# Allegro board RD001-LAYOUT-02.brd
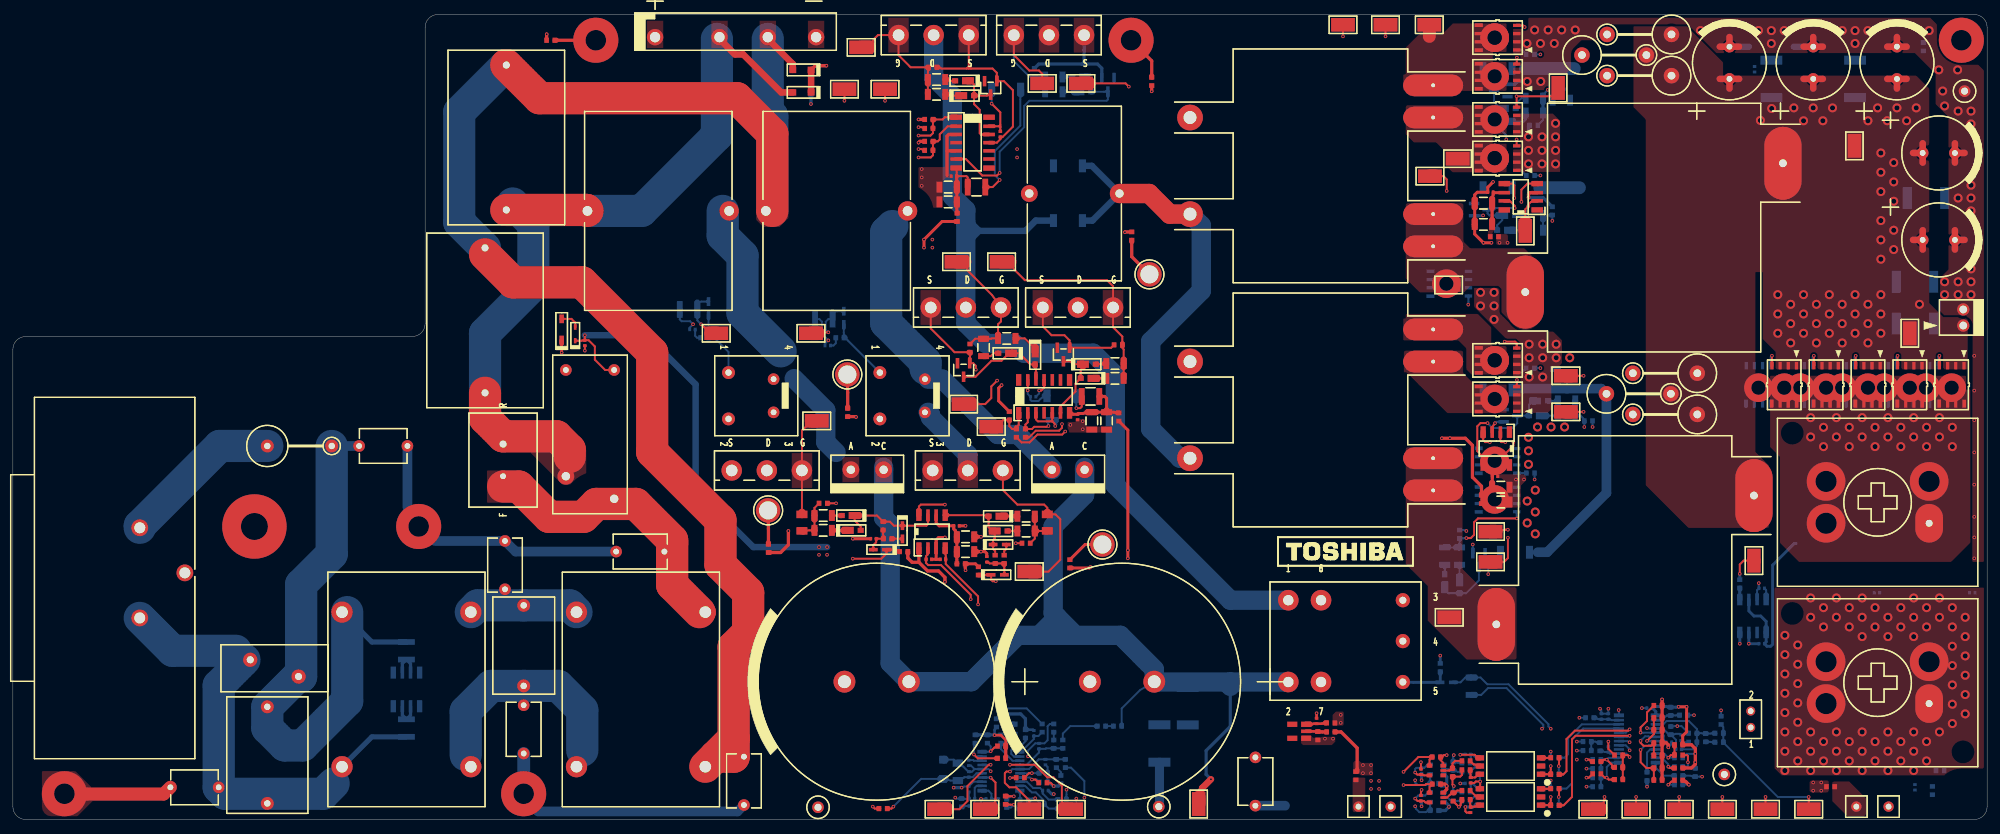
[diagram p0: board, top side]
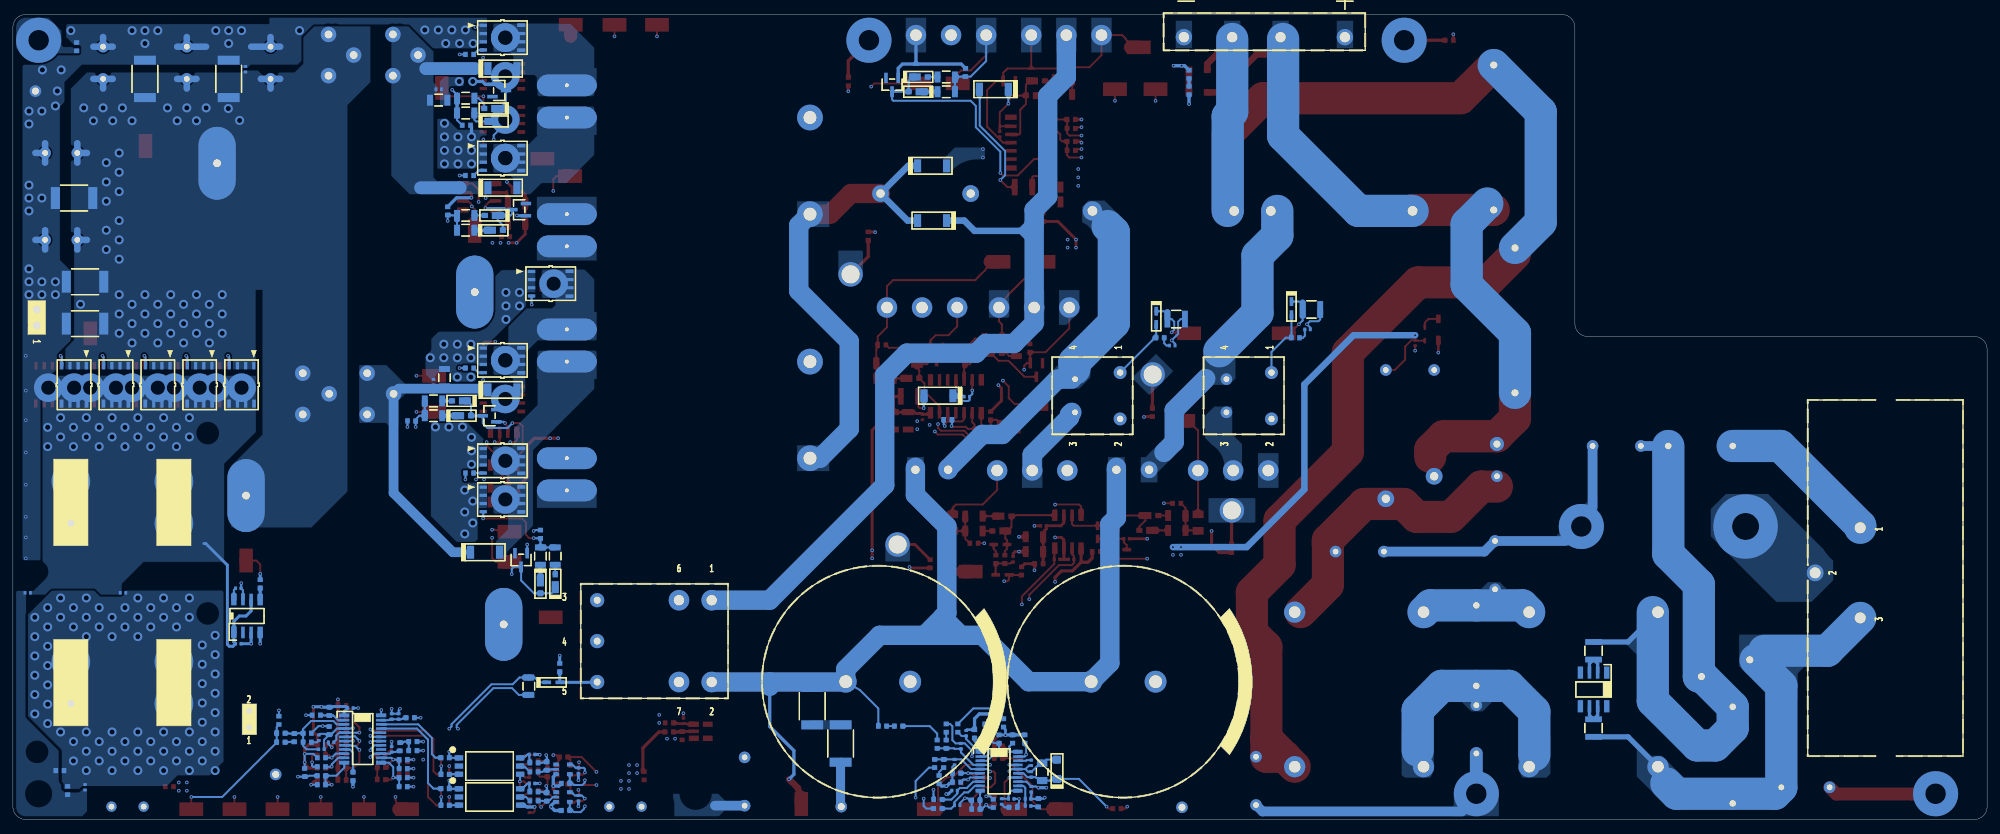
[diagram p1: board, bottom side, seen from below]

Outline 306.5 x 125 mm; copper layers: TOP, CONDUCTIVE2, CONDUCTIVE3, CONDUCTIVE4, CONDUCTIVE5, BOTTOM. Coordinates in mm from the lower left corner of the outline.
Outline path: 0,73 0.03,73.35 0.12,73.68 0.27,74 0.47,74.29 0.71,74.53 1,74.73 1.32,74.88 1.65,74.97 2,75 62,75 62.35,75.03 62.68,75.12 63,75.27 63.29,75.47 63.53,75.71 63.73,76 63.88,76.32 63.97,76.65 64,77 64,123 64.03,123.35 64.12,123.68 64.27,124 64.47,124.29 64.71,124.53 65,124.73 65.32,124.88 65.65,124.97 66,125 304.5,125 304.85,124.97 305.18,124.88 305.5,124.73 305.79,124.53 306.03,124.29 306.23,124 306.38,123.68 306.47,123.35 306.5,123 306.5,2 306.47,1.65 306.38,1.32 306.23,1 306.03,0.71 305.79,0.47 305.5,0.27 305.18,0.12 304.85,0.03 304.5,0 2,0 1.65,0.03 1.32,0.12 1,0.27 0.71,0.47 0.47,0.71 0.27,1 0.12,1.32 0.03,1.65 0,2 0,73

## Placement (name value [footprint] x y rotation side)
C1  -  [FTP_11]  172.2 21.4 0 top
C2  -  [FTP_13]  279.5 120 270 top
C3  -  [FTP_13]  292.5 120 270 top
C4  -  [FTP_13]  301.5 103.5 180 top
C5  -  [FTP_13]  301.5 90 180 top
C6  -  [FTP_13]  266.5 120 270 top
C7  -  [FTP_11]  134.1 21.4 0 top
C18  -  [FTP_65]  153.3 106.4 90 top
C19  -  [FTP_65#2]  158.4 65.65 0 bottom
C20  -  [FTP_67#2]  262.8 12.7 90 bottom
C21  -  [FTP_65#2]  259 12.7 270 bottom
C22  -  [FTP_65#2]  258.6 10.9 0 bottom
C23  -  [FTP_65#2]  246.6 16 90 bottom
C24  -  [FTP_65#2]  247.7 16 90 bottom
C25  -  [FTP_65#2]  257.1 12 0 bottom
C26  -  [FTP_65#2]  247.7 10.9 90 bottom
C27  -  [FTP_65#2]  240.4 113.4 180 bottom
C30  -  [FTP_77]  39.5 10 90 top
C31  -  [FTP_35]  79.3 14 90 top
C32  -  [FTP_35]  76.4 39.5 270 top
C33  -  [FTP_75]  76.6 105.9 270 top
C34  -  [FTP_65#2]  126.5 73.6 180 bottom
C35  -  [FTP_65]  151.2 40.4 270 top
C36  -  [FTP_65#2]  105.5 76.1 180 bottom
C37  -  [FTP_65]  133.6 43.6 0 top
C38  -  [FTP_65#2]  160.3 8.91 270 bottom
C39  -  [FTP_65#2]  159.3 11.4 90 bottom
C40  -  [FTP_67#2]  153.4 12.5 90 bottom
C41  -  [FTP_23]  155.3 14 90 bottom
C42  -  [FTP_65#2]  148.4 4.7 270 bottom
C43  -  [FTP_65#2]  148.9 3.2 180 bottom
C44  -  [FTP_65#2]  148.9 2.1 180 bottom
C45  -  [FTP_65#2]  151.5 3.2 180 bottom
C46  -  [FTP_65#2]  153 2.8 270 bottom
C47  -  [FTP_65#2]  148.4 7 90 bottom
C48  -  [FTP_24]  146.7 7.4 90 bottom
C49  -  [FTP_65#2]  148.4 8.8 270 bottom
C50  -  [FTP_65#2]  158.5 13.4 90 bottom
C51  -  [FTP_65#2]  241.2 67.9 90 bottom
C52  -  [FTP_73]  79.3 27 90 top
C53  -  [FTP_67]  142.2 105.3 0 top
C54  -  [FTP_67]  142.2 108.7 0 top
C55  -  [FTP_65]  146.1 99.9 0 top
C56  -  [FTP_67#2]  161.35 62.1 0 bottom
C57  -  [FTP_67]  154.7 62.7 270 top
C58  -  [FTP_65]  165.3 62.5 90 top
C59  -  [FTP_65#2]  271.5 35.9 0 bottom
C60  -  [FTP_65]  230.1 53.3 180 top
C61  -  [FTP_65]  229.4 97.4 0 top
C62  -  [FTP_65]  146.5 45.6 180 top
C63  -  [FTP_35]  113.5 6 90 top
C64  -  [FTP_35]  97.4 41.6 0 top
C65  -  [FTP_75]  73.3 77.5 270 top
C66  -  [FTP_67]  202.6 13 90 top
C67  -  [FTP_65]  202.4 15.3 270 top
C70  -  [FTP_65]  88.8 74 90 top
C71  -  [FTP_65#2]  225.9 10.1 180 bottom
C72  -  [FTP_65#2]  225.9 5.6 180 bottom
C73  -  [FTP_65]  226.3 6.1 90 top
C74  -  [FTP_65]  226.3 1.5 90 top
C75  -  [FTP_65#2]  160.3 4.5 0 bottom
C76  -  [FTP_65#2]  159.9 2.2 180 bottom
C77  -  [FTP_67#2]  157 3 0 bottom
C78  -  [FTP_33]  57.5 58 180 top
C79  -  [FTP_33]  28.2 5 0 top
C80  -  [FTP_65]  144.4 40.4 0 top
C81  -  [FTP_65]  142.2 40.4 180 top
C82  -  [FTP_15]  147.9 43.9 180 top
C83  -  [FTP_15]  147.9 41.6 180 top
C84  -  [FTP_15]  167.5 61.9 90 top
C85  -  [FTP_15]  169.8 61.9 90 top
C86  -  [FTP_15]  145.2 95.9 0 top
C87  -  [FTP_15]  145.2 98.2 0 top
C88  -  [FTP_15]  228.3 95.7 0 top
C89  -  [FTP_15]  228.3 92.4 0 top
C90  -  [FTP_15]  231 49.3 180 top
C91  -  [FTP_15]  231 51.6 180 top
C92  -  [FTP_65#2]  289.4 35.2 180 bottom
C93  -  [FTP_65#2]  304.2 35.2 0 bottom
C94  -  [FTP_65#2]  295.3 5 90 bottom
C95  -  [FTP_65#2]  218.7 7.6 270 bottom
C96  -  [FTP_65#2]  218.7 3.3 270 bottom
C97  -  [FTP_65]  218.6 7.4 270 top
C98  -  [FTP_65]  218.6 3.3 270 top
C99  -  [FTP_65#2]  254.1 17.3 180 bottom
C100  -  [FTP_65#2]  271.5 27.3 180 bottom
C101  -  [FTP_33]  192.9 5.9 270 top
C102  -  [FTP_65#2]  270.4 116.5 90 bottom
CN1  -  [FTP_9]  3.9 37.5 270 top
CN2  -  [FTP_5]  208.9 2 0 top
CN3  -  [FTP_5]  213.9 2 0 top
CN4  -  [FTP_5]  286.2 2 0 top
CN5  -  [FTP_5]  291.2 2 0 top
CN6  -  [FTP_92]  289.5 49.25 90 top
CN7  -  [FTP_92]  289.5 21.25 90 top
CN8  -  [FTP_3]  302.8 76.7 90 top
CN10  -  [FTP_7]  269.8 14.3 0 top
D1  -  [FTP_53]  130.1 54.31 0 top
D2  -  [FTP_53]  161.3 54.31 0 top
D3  -  [FTP_17]  99.7 121.48 0 top
D8  -  [FTP_29]  122.5 112.9 0 top
D9  -  [FTP_29]  122.5 116.4 0 top
D12  -  [FTP_20]  129 77.9 90 bottom
D13  -  [FTP_20]  108 79.4 90 bottom
D14  -  [FTP_20]  222.6 21.3 0 bottom
D16  -  [FTP_81]  154.2 113.4 180 bottom
D17  -  [FTP_81]  162.8 65.8 180 bottom
D18  -  [FTP_81]  163.8 101.5 0 bottom
D19  -  [FTP_81]  163.8 93 180 bottom
D20  -  [FTP_81]  230.5 98.1 0 bottom
D21  -  [FTP_81]  230.5 116.6 0 bottom
D22  -  [FTP_27]  170 114.1 0 bottom
D23  -  [FTP_27]  151.8 113.6 180 top
D24  -  [FTP_27]  147.6 69.8 180 top
D25  -  [FTP_27]  163.1 72.2 180 top
D26  -  [FTP_27]  227.9 94.7 90 bottom
D27  -  [FTP_27]  231 113.2 270 bottom
D28  -  [FTP_27]  232.5 62.7 90 bottom
D29  -  [FTP_27]  227.6 40.3 0 bottom
D30  -  [FTP_20]  153.2 42.7 180 top
D31  -  [FTP_20]  152.9 38 180 top
D32  -  [FTP_20]  138.1 44.6 90 top
D33  -  [FTP_20]  134.6 41.9 0 top
D34  -  [FTP_81]  233.2 41.5 0 bottom
D35  -  [FTP_81]  230.5 66.7 0 bottom
D36  -  [FTP_83]  152.7 47.1 0 top
D37  -  [FTP_83]  153.2 44.8 180 top
D38  -  [FTP_83]  130.4 44.9 180 top
D39  -  [FTP_83]  129.9 47.2 0 top
D40  -  [FTP_83]  158.7 71.9 90 top
D41  -  [FTP_83]  154.2 72.4 0 top
D42  -  [FTP_83]  148 112.4 180 top
D43  -  [FTP_83]  147.5 114.7 0 top
D44  -  [FTP_83]  167 68.5 0 top
D45  -  [FTP_83]  166.9 70.7 180 top
D46  -  [FTP_83]  166.2 113 180 bottom
D47  -  [FTP_83]  165.7 115.3 0 bottom
D48  -  [FTP_28]  87.3 75.4 270 top
D49  -  [FTP_85]  144.4 7.8 270 bottom
D50  -  [FTP_19]  85.2 76.1 270 top
D51  -  [FTP_83]  231.6 108.4 0 bottom
D52  -  [FTP_83]  232.1 110.4 180 bottom
D53  -  [FTP_83]  231.65 91.5 0 bottom
D54  -  [FTP_83]  232 93.8 180 bottom
D55  -  [FTP_83]  236.6 62.7 0 bottom
D56  -  [FTP_83]  237.1 65 180 bottom
D57  -  [FTP_83]  224.6 36.35 90 bottom
D58  -  [FTP_83]  222.3 36.85 270 bottom
F1  -  [FTP_79]  39.5 58 0 top
FB1  -  [FTP_55]  160.6 46.1 90 top
FB2  -  [FTP_55]  122.5 46.1 90 top
HS1  -  [FTP_116]  129.55 69.1 0 top
HS2  -  [FTP_116]  169.15 42.7 0 top
HS3  -  [FTP_116]  117.25 48 0 top
HS4  -  [FTP_116]  176.45 84.65 0 top
IC1  -  [FTP_60]  61.1 20.2 180 bottom
IC2  -  [FTP_112]  142.7 44.7 0 top
IC3  -  [FTP_128]  153.4 7.5 270 bottom
IC4  -  [FTP_59]  160.1 65.7 0 top
IC5  -  [FTP_59]  149 105.1 270 top
IC6  -  [FTP_112]  234.1 96.7 90 top
IC7  -  [FTP_112]  230.3 57.6 180 top
IC8  -  [FTP_112]  270.15 31.6 180 bottom
IC10  -  [FTP_61]  252.2 12.5 90 bottom
IC11  -  [FTP_38]  199.7 13.7 90 top
IC13  -  [FTP_122]  232.5 8.3 270 bottom
IC14  -  [FTP_122]  232.5 3.5 270 bottom
IC15  -  [FTP_122]  232.5 8.3 90 top
IC16  -  [FTP_122]  232.5 3.5 90 top
IC20  -  [FTP_100]  89.6 59.8 270 top
IC21  -  [FTP_37#2]  221.1 7.8 90 bottom
IC22  -  [FTP_37#2]  221.1 3.5 90 bottom
IC23  -  [FTP_37]  221 7.6 90 top
IC24  -  [FTP_37]  221 3.4 90 top
L1  -  [FTP_118]  100.2 94.5 270 top
L2  -  [FTP_118]  127.9 94.5 270 top
L3  -  [FTP_69]  164.8 97.2 270 top
L5  -  [FTP_124]  250.3 40.3 270 top
L6  -  [FTP_124]  254.8 91.9 270 top
L11  -  [FTP_110]  61.1 20.2 270 top
L12  -  [FTP_110]  97.5 20.2 270 top
NOREF  -  []  302.5 121 0 top
NOREF#2  -  []  173.6 121 0 top
NOREF#3  -  []  196.4 39.4 0 top
NOREF#4  -  []  90.5 121 0 top
NOREF#5  -  []  200.5 4 0 top
NOREF#6  -  []  302.5 4 0 top
NOREF#7  -  []  63 45.5 0 top
NOREF#8  -  []  37.5 45.5 0 top
NOREF#9  -  []  8 4 0 top
NOREF#10  -  []  8 71 0 top
NOREF#11  -  []  79.3 4 0 top
Q1  -  [FTP_102]  111.6 54.2 0 top
Q2  -  [FTP_102]  142.8 54.2 0 top
Q3  -  [FTP_102]  142.5 79.5 0 top
Q4  -  [FTP_102]  159.9 79.5 0 top
Q5  -  [FTP_102]  148.4 121.8 180 top
Q6  -  [FTP_102]  166.3 121.8 180 top
Q7  -  [FTP_1]  230.5 71.3 90 top
Q8  -  [FTP_1]  223 83.2 270 bottom
Q9  -  [FTP_1]  230.5 49.7 270 bottom
Q10  -  [FTP_1]  230.5 55.7 270 bottom
Q11  -  [FTP_1]  230.5 121.4 90 top
Q12  -  [FTP_1]  230.5 115.4 90 top
Q13  -  [FTP_1]  230.5 108.7 90 top
Q14  -  [FTP_1]  230.5 102.7 270 bottom
Q15  -  [FTP_1]  301 67.5 180 top
Q16  -  [FTP_1]  294.5 67.5 180 top
Q17  -  [FTP_1]  288 67.5 180 top
Q18  -  [FTP_1]  281.5 67.5 180 top
Q19  -  [FTP_1]  275 67.5 180 top
Q20  -  [FTP_1]  297 67.5 0 bottom
Q21  -  [FTP_1]  290.5 67.5 0 bottom
Q22  -  [FTP_1]  284 67.5 0 bottom
Q23  -  [FTP_1]  277.5 67.5 0 bottom
Q24  -  [FTP_1]  271 67.5 0 bottom
Q25  -  [FTP_1]  230.5 121.4 270 bottom
Q26  -  [FTP_1]  230.5 102.7 90 top
Q27  -  [FTP_1]  230.5 65.3 90 top
Q28  -  [FTP_1]  230.5 71.3 270 bottom
R1  -  [FTP_67#2]  163.4 8.7 90 bottom
R2  -  [FTP_67#2]  162.7 6.2 270 bottom
R6  -  [FTP_67#2]  268.1 36.6 270 bottom
R7  -  [FTP_49#2]  104.9 79.2 180 bottom
R8  -  [FTP_49#2]  125.9 77.7 180 bottom
R9  -  [FTP_67#2]  221.6 23.6 90 bottom
R18  -  [FTP_50#2]  236.2 109.7 180 bottom
R19  -  [FTP_67#2]  236.1 107.8 180 bottom
R20  -  [FTP_50#2]  236.2 91.5 180 bottom
R21  -  [FTP_67#2]  239 94.5 90 bottom
R22  -  [FTP_67#2]  244.6 61.9 0 bottom
R23  -  [FTP_50#2]  241.2 62.7 180 bottom
R24  -  [FTP_50#2]  224.6 40.9 270 bottom
R25  -  [FTP_67#2]  224.6 44.3 90 bottom
R28  -  [FTP_67]  142.8 116.8 180 top
R29  -  [FTP_67#2]  158.6 116 90 bottom
R31  -  [FTP_67]  148.6 73.2 90 top
R33  -  [FTP_67]  171.6 73.7 0 top
R42  -  [FTP_67#2]  264.9 13.4 180 bottom
R43  -  [FTP_67#2]  260.8 13.4 180 bottom
R44  -  [FTP_67#2]  257.4 16.8 270 bottom
R45  -  [FTP_67#2]  259.4 16.2 0 bottom
R46  -  [FTP_67#2]  264.9 12 180 bottom
R47  -  [FTP_67#2]  260.8 12 180 bottom
R48  -  [FTP_67#2]  257.4 13.8 90 bottom
R49  -  [FTP_67#2]  244.8 15.8 180 bottom
R50  -  [FTP_67]  255.4 17.7 180 top
R51  -  [FTP_67]  255.4 9.9 180 top
R52  -  [FTP_67]  255.4 13.9 180 top
R53  -  [FTP_67]  255.4 8 180 top
R54  -  [FTP_67#2]  253.7 6.7 270 bottom
R55  -  [FTP_67]  258.6 10 180 top
R56  -  [FTP_67#2]  258.6 8.2 0 bottom
R57  -  [FTP_67#2]  258.6 9.6 180 bottom
R58  -  [FTP_67]  258.6 8 0 top
R59  -  [FTP_67#2]  244.4 12.1 180 bottom
R60  -  [FTP_67#2]  258.6 6.8 180 bottom
R61  -  [FTP_67#2]  258.6 5.4 0 bottom
R62  -  [FTP_67#2]  261.2 7.3 270 bottom
R63  -  [FTP_67]  249.3 6.2 0 top
R64  -  [FTP_67#2]  245.9 6.5 180 bottom
R65  -  [FTP_67]  249.3 8.1 0 top
R66  -  [FTP_67#2]  245.9 9.3 180 bottom
R67  -  [FTP_67#2]  244.4 10.7 0 bottom
R69  -  [FTP_67#2]  246.4 11.3 270 bottom
R70  -  [FTP_67]  249.3 10 0 top
R71  -  [FTP_67]  157.3 42.9 0 top
R72  -  [FTP_50]  157.3 47.1 0 top
R73  -  [FTP_67]  125.8 49.1 180 top
R74  -  [FTP_50]  125.8 44.9 180 top
R75  -  [FTP_67#2]  265.2 15.4 270 bottom
R76  -  [FTP_50#2]  240.4 111.7 180 bottom
R77  -  [FTP_98]  257.5 121.9 180 top
R78  -  [FTP_98]  257.5 115.5 180 top
R79  -  [FTP_49#2]  61.1 26.2 270 bottom
R80  -  [FTP_49#2]  61.1 14.2 270 bottom
R81  -  [FTP_67#2]  128.4 74.8 180 bottom
R82  -  [FTP_67]  152.5 40.4 270 top
R83  -  [FTP_67]  149.9 38.6 90 top
R85  -  [FTP_67#2]  107.4 74.8 180 bottom
R86  -  [FTP_67]  135.1 45.6 270 top
R87  -  [FTP_67]  138.3 41.6 0 top
R89  -  [FTP_67#2]  163 11.7 270 bottom
R90  -  [FTP_67#2]  161.6 14.2 90 bottom
R91  -  [FTP_67#2]  169 14.5 180 bottom
R92  -  [FTP_67#2]  171.5 14.5 180 bottom
R93  -  [FTP_67#2]  152.7 15 270 bottom
R94  -  [FTP_67#2]  123.9 113.2 270 bottom
R95  -  [FTP_67#2]  123.9 115.7 270 bottom
R96  -  [FTP_67#2]  157 1.6 0 bottom
R97  -  [FTP_67#2]  154.3 2.5 270 bottom
R98  -  [FTP_67#2]  147.3 2.6 90 bottom
R99  -  [FTP_67#2]  151.2 1.9 180 bottom
R100  -  [FTP_67#2]  149.4 12.5 90 bottom
R101  -  [FTP_67#2]  160 5.8 0 bottom
R102  -  [FTP_67#2]  160 7.2 0 bottom
R103  -  [FTP_67#2]  151.3 12.5 90 bottom
R104  -  [FTP_67#2]  157.2 13.3 90 bottom
R105  -  [FTP_50#2]  239.5 68.6 90 bottom
R106  -  [FTP_98]  261.5 69.3 180 top
R107  -  [FTP_98]  247.4 66.1 0 top
R108  -  [FTP_50]  157.3 44.8 0 top
R109  -  [FTP_50]  125.8 47.2 180 top
R110  -  [FTP_67]  142.2 103.9 0 top
R111  -  [FTP_67]  142.2 107.3 0 top
R112  -  [FTP_67]  157.2 60 90 top
R113  -  [FTP_67]  155.8 60 90 top
R114  -  [FTP_49]  149.6 98.2 0 top
R115  -  [FTP_49]  167.3 65.7 180 top
R116  -  [FTP_67]  208.5 6.8 90 top
R117  -  [FTP_67]  204.6 15 0 top
R118  -  [FTP_67]  282.2 5.1 180 top
R120  -  [FTP_67]  135.1 1.7 0 top
R121  -  [FTP_67]  147.2 39.7 180 top
R122  -  [FTP_67]  171.7 62.5 90 top
R123  -  [FTP_67]  146.6 93.5 90 top
R124  -  [FTP_67]  228 49.7 270 top
R125  -  [FTP_67]  230 90.5 180 top
R126  -  [FTP_50]  154.3 74.7 180 top
R127  -  [FTP_50]  150.7 73.3 90 top
R128  -  [FTP_98]  243.6 118.7 0 top
R129  -  [FTP_98]  261.5 62.9 180 top
R130  -  [FTP_67]  204.6 13.6 180 top
R132  -  [FTP_50]  143.4 112.6 180 top
R133  -  [FTP_50]  143.4 114.9 180 top
R134  -  [FTP_50]  171.1 68.5 0 top
R135  -  [FTP_50]  171.1 70.8 0 top
R136  -  [FTP_50#2]  161.6 113 0 bottom
R137  -  [FTP_50#2]  161.6 115.3 0 bottom
R138  -  [FTP_108]  76.1 55.8 90 top
R149  -  [FTP_67#2]  239.4 9.6 180 bottom
R150  -  [FTP_67#2]  239.4 4.8 180 bottom
R151  -  [FTP_67]  239.4 7 0 top
R152  -  [FTP_67]  239.4 2.2 0 top
R153  -  [FTP_67#2]  225.6 7.4 180 bottom
R154  -  [FTP_67#2]  225.6 2.9 180 bottom
R155  -  [FTP_67]  225.6 9.1 0 top
R156  -  [FTP_67]  225.6 4.5 0 top
R157  -  [FTP_67#2]  225.6 8.8 180 bottom
R160  -  [FTP_67#2]  225.6 4.3 180 bottom
R163  -  [FTP_67]  225.6 7.7 0 top
R166  -  [FTP_67]  225.6 3.1 0 top
R169  -  [FTP_67#2]  162.9 3.1 0 bottom
R170  -  [FTP_67#2]  162.9 1.7 0 bottom
R171  -  [FTP_67#2]  159.8 14.2 270 bottom
R172  -  [FTP_67]  153.9 40.4 270 top
R173  -  [FTP_67]  135.8 43.6 180 top
R174  -  [FTP_67]  153.5 11.4 180 top
R175  -  [FTP_67]  156.4 6.5 0 top
R176  -  [FTP_67]  159.9 5.7 180 top
R177  -  [FTP_67]  154.1 3 90 top
R178  -  [FTP_106]  182.4 17.6 270 bottom
R179  -  [FTP_106]  178 11.8 270 bottom
R180  -  [FTP_67]  255.4 11.9 180 top
R181  -  [FTP_67]  255.4 15.8 180 top
R182  -  [FTP_67]  255.4 6.1 180 top
R184  -  [FTP_67]  258.6 6.1 180 top
R185  -  [FTP_50#2]  226.4 20.7 270 bottom
R186  -  [FTP_67#2]  223.6 8.3 270 bottom
R187  -  [FTP_67#2]  220.7 5.6 0 bottom
R188  -  [FTP_67#2]  223.6 3.5 270 bottom
R189  -  [FTP_67#2]  220.7 1.4 0 bottom
R190  -  [FTP_67]  223.5 7.3 270 top
R191  -  [FTP_67]  221 9.7 180 top
R192  -  [FTP_67]  223.6 3.5 270 top
R193  -  [FTP_67]  221 5.5 180 top
R194  -  [FTP_67#2]  239.4 7 180 bottom
R195  -  [FTP_67#2]  239.4 2.2 180 bottom
R196  -  [FTP_67]  239.4 9.6 0 top
R197  -  [FTP_67]  239.4 4.8 0 top
R198  -  [FTP_67]  153.5 9.5 180 top
R199  -  [FTP_106]  295.3 77 0 bottom
R200  -  [FTP_106]  273 115 90 bottom
R201  -  [FTP_106]  286 115 90 bottom
R202  -  [FTP_106]  295.3 83.5 0 bottom
R203  -  [FTP_106]  297 96.5 0 bottom
R204  -  [FTP_67#2]  296.6 120 270 bottom
R205  -  [FTP_67#2]  299.2 7.6 0 bottom
R206  -  [FTP_67#2]  298 4.5 270 bottom
R207  -  [FTP_67]  258.6 11.6 0 top
R208  -  [FTP_67]  245.9 7.1 0 top
R209  -  [FTP_67]  245.9 9 0 top
R210  -  [FTP_67#2]  245.9 5.1 0 bottom
R211  -  [FTP_67#2]  245.9 7.9 0 bottom
R212  -  [FTP_50#2]  236.2 112 180 bottom
R213  -  [FTP_50#2]  236.2 93.8 180 bottom
R214  -  [FTP_50#2]  241.2 65 180 bottom
R215  -  [FTP_50#2]  222.3 40.9 270 bottom
R216  -  [FTP_67#2]  235.6 118.8 0 bottom
R217  -  [FTP_67#2]  235.6 100 0 bottom
R218  -  [FTP_67#2]  235.6 70.1 0 bottom
R219  -  [FTP_67#2]  235.6 53.8 0 bottom
R220  -  [FTP_67]  129.6 63.2 90 top
R221  -  [FTP_67]  164.1 39.7 90 top
R222  -  [FTP_67]  117.3 42.1 90 top
R223  -  [FTP_67]  173.7 90.6 270 top
R224  -  [FTP_67]  176.8 114.6 90 top
R225  -  [FTP_67]  83.5 121 0 top
R227  -  [FTP_67#2]  161.6 11.7 90 bottom
R228  -  [FTP_67#2]  162 8.7 270 bottom
RV1  -  [FTP_120]  40.6 23.5 180 top
T2  -  [FTP_94]  138.9 65.8 270 top
T3  -  [FTP_94]  115.4 65.8 270 top
T4  -  [FTP_96]  206.9 27.7 0 top
T5  -  [FTP_126]  203 63.6 0 top
T6  -  [FTP_126]  203 101.5 0 top
TP1  -  [FTP_57]  123.9 75.5 0 top
TP2  -  [FTP_57]  109.2 75.5 0 top
TP3  -  [FTP_57]  157.8 38.5 0 top
TP4  -  [FTP_57]  124.8 61.9 0 top
TP5  -  [FTP_57]  150.9 1.6 0 top
TP6  -  [FTP_57]  143.8 1.6 0 top
TP7  -  [FTP_57]  157.8 1.6 0 top
TP8  -  [FTP_57]  164.3 1.6 0 top
TP9  -  [FTP_57]  151.9 61 0 top
TP10  -  [FTP_57]  147.6 64.5 0 top
TP11  -  [FTP_57]  146.5 86.6 0 top
TP12  -  [FTP_57]  153.5 86.6 0 top
TP13  -  [FTP_57]  131.7 119.9 0 top
TP14  -  [FTP_57]  159.8 114.3 180 top
TP15  -  [FTP_57]  165.8 114.3 0 top
TP17  -  [FTP_57]  222.9 83 0 top
TP18  -  [FTP_57]  223 31.4 180 top
TP19  -  [FTP_57]  239.9 113.6 90 top
TP20  -  [FTP_57]  241.1 63.3 0 top
TP21  -  [FTP_57]  213.1 123.4 0 top
TP22  -  [FTP_57]  241.1 68.9 0 top
TP23  -  [FTP_57]  234.8 91.4 270 top
TP24  -  [FTP_57]  220 99.9 0 top
TP25  -  [FTP_57]  229.4 40 0 top
TP26  -  [FTP_57]  229.4 44.7 0 top
TP27  -  [FTP_57]  206.5 123.4 0 top
TP28  -  [FTP_57]  270.3 40.2 90 top
TP29  -  [FTP_57]  224.3 102.6 0 top
TP30  -  [FTP_57]  219.9 123.4 0 top
TP31  -  [FTP_57]  294.5 75.5 90 top
TP32  -  [FTP_57]  272.1 1.6 0 top
TP33  -  [FTP_57]  278.8 1.6 0 top
TP34  -  [FTP_57]  265.4 1.6 0 top
TP35  -  [FTP_57]  252 1.6 0 top
TP36  -  [FTP_57]  258.7 1.6 0 top
TP37  -  [FTP_57]  245.3 1.6 0 top
TP38  -  [FTP_57]  135.4 113.4 0 top
TP39  -  [FTP_57]  129.1 113.4 0 top
TP40  -  [FTP_57]  285.9 104.6 90 top
TP41  -  [FTP_71]  303 113.1 0 top
TP42  -  [FTP_71]  265.7 7 0 top
TP43  -  [FTP_71]  125 1.9 0 top
TP44  -  [FTP_57]  184.1 2.4 90 top
TP45  -  [FTP_71]  177.9 2 0 top

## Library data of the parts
C1 C7 = PRT_4: alternate symbols: (T:FTP_11;B:FTP_12)
C2-C6 = PRT_3: alternate symbols: (T:FTP_13;B:FTP_14)
C18 C19 C21-C27 C34-C39 C42-C47 C49-C51 C55 C58-C62 C67 C70-C76 C80 C81 C92-C100 C102 = PRT_52: alternate symbols: (T:FTP_65;B:FTP_66)
C20 C40 C53 C54 C56 C57 C66 C77 = PRT_48: alternate symbols: (T:FTP_67;B:FTP_68)
C30 = PRT_19: alternate symbols: (T:FTP_77;B:FTP_78)
C31 C32 C63 C64 = PRT_13: alternate symbols: (T:FTP_35;B:FTP_36)
C33 C65 = PRT_18: alternate symbols: (T:FTP_75;B:FTP_76)
C41 = PRT_32: alternate symbols: (T:FTP_23,FTP_44;B:FTP_26,FTP_48)
C48 = PRT_51: alternate symbols: (T:FTP_24;B:FTP_25)
C52 = PRT_17: alternate symbols: (T:FTP_73;B:FTP_74)
C78 C79 = PRT_29: alternate symbols: (T:FTP_33;B:FTP_34)
C82-C91 = PRT_46: alternate symbols: (T:FTP_15;B:FTP_16)
C101 = PRT_50: alternate symbols: (T:FTP_33;B:FTP_34)
CN1 = PRT_61: alternate symbols: (T:FTP_9;B:FTP_10)
CN2-CN5 = PRT_57: alternate symbols: (T:FTP_5;B:FTP_6)
CN6 CN7 = PRT_38: alternate symbols: (T:FTP_92;B:FTP_93)
CN8 = PRT_42: alternate symbols: (T:FTP_3;B:FTP_4)
CN10 = PRT_56: alternate symbols: (T:FTP_7;B:FTP_8)
D1 D2 = PRT_12: alternate symbols: (T:FTP_53;B:FTP_54)
D3 = PRT_53: alternate symbols: (T:FTP_17,FTP_18;B:FTP_87,FTP_88)
D8 D9 = PRT_24: alternate symbols: (T:FTP_29;B:FTP_30)
D12-D14 D30-D33 = PRT_27: alternate symbols: (T:FTP_20;B:FTP_22)
D16-D21 D34 D35 = PRT_14: alternate symbols: (T:FTP_81;B:FTP_82)
D22-D29 = PRT_25: alternate symbols: (T:FTP_27,FTP_41;B:FTP_31,FTP_45)
D36-D47 D51-D58 = PRT_11: alternate symbols: (T:FTP_83;B:FTP_84)
D48 = PRT_26: alternate symbols: (T:FTP_28;B:FTP_32)
D49 = PRT_6: alternate symbols: (T:FTP_85;B:FTP_86)
D50 = PRT_47: alternate symbols: (T:FTP_19;B:FTP_21)
F1 = PRT_21: alternate symbols: (T:FTP_79;B:FTP_80)
FB1 FB2 = PRT_30: alternate symbols: (T:FTP_55;B:FTP_56)
HS1-HS4 = PRT_39: alternate symbols: (T:FTP_116;B:FTP_117)
IC1 = PRT_45: alternate symbols: (T:FTP_60;B:FTP_63)
IC2 IC6 IC7 = PRT_63: alternate symbols: (T:FTP_112;B:FTP_113)
IC3 = PRT_59: alternate symbols: (T:FTP_128;B:FTP_129)
IC4 IC5 = PRT_58: alternate symbols: (T:FTP_59;B:FTP_62)
IC8 = PRT_62: alternate symbols: (T:FTP_112;B:FTP_113)
IC10 = PRT_16: alternate symbols: (T:FTP_61;B:FTP_64)
IC11 = PRT_10: alternate symbols: (T:FTP_38,FTP_42;B:FTP_40,FTP_46)
IC13-IC16 = PRT_15: alternate symbols: (T:FTP_122;B:FTP_123)
IC20 = PRT_1: alternate symbols: (T:FTP_100;B:FTP_101)
IC21-IC24 = PRT_2: alternate symbols: (T:FTP_37,FTP_43;B:FTP_39,FTP_47)
L1 L2 = PRT_41: alternate symbols: (T:FTP_118;B:FTP_119)
L3 = PRT_64: alternate symbols: (T:FTP_69;B:FTP_70)
L5 L6 = PRT_40: alternate symbols: (T:FTP_124;B:FTP_125)
L11 L12 = PRT_22: alternate symbols: (T:FTP_110;B:FTP_111)
Q1 Q2 = PRT_31: alternate symbols: (T:FTP_102,FTP_105,FTP_103;B:FTP_89,FTP_104,FTP_90)
Q3-Q6 = PRT_9: alternate symbols: (T:FTP_102,FTP_105,FTP_103;B:FTP_89,FTP_104,FTP_90)
Q7-Q14 Q25-Q28 = PRT_67: alternate symbols: (T:FTP_1;B:FTP_2)
Q15-Q24 = PRT_60: alternate symbols: (T:FTP_1;B:FTP_2)
R1 R2 R6 R9 R19 R21 R22 R25 R28 R29 R31 R33 R42-R67 R69-R71 R73 R75 R81-R83 R85-R87 R89-R104 R110-R113 R116-R118 R120-R125 R130 R149-R157 R160 R163 R166 R169-R177 R180-R182 R184 R186-R198 R204-R211 R216-R225 R227 R228 = PRT_8: alternate symbols: (T:FTP_67;B:FTP_68)
R7 R8 R79 R80 R114 R115 = PRT_23: alternate symbols: (T:FTP_49;B:FTP_52)
R18 R20 R23 R24 R72 R74 R76 R105 R108 R109 R126 R127 R132-R137 R185 R212-R215 = PRT_5: alternate symbols: (T:FTP_50;B:FTP_51)
R77 R78 R106 R107 R128 R129 = PRT_54: alternate symbols: (T:FTP_98;B:FTP_99)
R138 = PRT_33: alternate symbols: (T:FTP_108;B:FTP_109)
R178 R179 R199-R203 = PRT_43: alternate symbols: (T:FTP_106;B:FTP_107)
RV1 = PRT_37: alternate symbols: (T:FTP_120;B:FTP_121)
T2 T3 = PRT_7: alternate symbols: (T:FTP_94;B:FTP_95)
T4 = PRT_65: alternate symbols: (T:FTP_96;B:FTP_97)
T5 T6 = PRT_55: alternate symbols: (T:FTP_126;B:FTP_127)
TP1-TP15 TP17-TP40 TP44 = PRT_44: alternate symbols: (T:FTP_57;B:FTP_58)
TP41 TP42 = PRT_34: alternate symbols: (T:FTP_71;B:FTP_72)
TP43 TP45 = PRT_49: alternate symbols: (T:FTP_71;B:FTP_72)

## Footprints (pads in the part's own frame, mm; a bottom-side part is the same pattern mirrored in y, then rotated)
FTP_1
  rect 0.5x1.15 smd: 1(-1.905,-2.975) 2(-0.635,-2.975) 3(0.635,-2.975) 4(1.905,-2.975)
  rect 0.57x1.25 smd: 5(1.94,2.925) 8(-1.94,2.925)
  rect 0.5x1.25 smd: 6(0.635,2.925) 7(-0.635,2.925)
FTP_3
  round 1.9 hole 1.2: 1(0,0) 2(2.5,0)
FTP_5
  round 1.6 hole 0.9: 1(0,0)
FTP_7
  round 1.4 hole 0.9: 1(0,0) 2(0,2.54)
FTP_9
  round 2.6 hole 1.7: 1(-7.8,15.8) 2(-0.8,22.8) 3(6.2,15.8)
FTP_11
  round 3.4 hole 2: 1(-5,0) 2(5,0)
FTP_13
  round 1.8 hole 0.9: 1(0,0) 2(5,0)
FTP_15
  rect 0.92x1.7 smd: 1(-1.35,0) 2(1.35,0)
FTP_17
  round 2.54 hole 1.6: 1(0,0) 2(10,0) 3(17.5,0) 4(25,0)
FTP_19
  rect 1.335x0.7 smd: A(-1.637,0) C(1.637,0)
FTP_20
  rect 1.36x0.55 smd: A(-1.025,0) C(1.025,0)
FTP_23
  rect 0.83x1.35 smd: 1(0.8,0) 2(-0.8,0)
FTP_24
  rect 1.1x1.6 smd: 1(1.35,0) 2(-1.35,0)
FTP_27
  rect 0.55x1.61 smd: A(-0.95,-1.05) C(0,1.05) NC(0.95,-1.05)
FTP_28
  rect 0.824x0.4 smd: A(-1.05,0) C(1.05,0)
FTP_29
  rect 1.074x1 smd: A(-1.425,0) C(1.425,0)
FTP_33
  round 1.8 hole 0.9: 1(-3.75,0) 2(3.75,0)
FTP_35
  round 1.8 hole 0.9: 1(-3.75,0) 2(3.75,0)
FTP_37
  rect 0.6x0.88 smd: 1(-0.75,-1.065) 3(0.75,-1.065) 4(0.75,1.065) 5(-0.75,1.065)
  rect 0.4x0.88 smd: 2(0,-1.065)
FTP_37#2
  rect 0.6x0.88 smd: 1(0.75,1.065) 3(-0.75,1.065) 4(-0.75,-1.065) 5(0.75,-1.065)
  rect 0.4x0.88 smd: 2(0,1.065)
FTP_38
  rect 0.825x1.56 smd: 1(-1.087,-1.075) 3(1.087,-1.075) 4(1.087,1.075) 5(-1.087,1.075)
  rect 0.55x1.56 smd: 2(0,-1.075)
FTP_49
  rect 0.895x2.6 smd: 1(-1.363,0) 2(1.363,0)
FTP_49#2
  rect 0.895x2.6 smd: 1(1.363,0) 2(-1.363,0)
FTP_50
  rect 0.92x1.7 smd: 1(-1.35,0) 2(1.35,0)
FTP_50#2
  rect 0.92x1.7 smd: 1(1.35,0) 2(-1.35,0)
FTP_53
  round 2.6 hole 1.3: A(0,0) C(5.08,0)
FTP_55
  rect 1.17x1.7 smd: 1(-1.275,0) 2(1.275,0)
FTP_57
  rect 3.7x2.1 smd: 1(0,0)
FTP_59
  rect 0.825x1.805 smd: 1(-3.947,-2.553) 7(3.947,-2.553) 8(3.947,2.553) 14(-3.947,2.553)
  rect 0.55x1.805 smd: 2(-2.54,-2.553) 3(-1.27,-2.553) 4(0,-2.553) 5(1.27,-2.553) 6(2.54,-2.553) 9(2.54,2.553) 10(1.27,2.553) 11(0,2.553) 12(-1.27,2.553) 13(-2.54,2.553)
FTP_60
  rect 0.825x1.885 smd: 1(2.042,2.612) 4(-2.042,2.612) 5(-2.042,-2.612) 8(2.042,-2.612)
  rect 0.55x1.885 smd: 2(0.635,2.612) 3(-0.635,2.612) 6(-0.635,-2.612) 7(0.635,-2.612)
FTP_61
  rect 0.6x1.585 smd: 1(3.675,2.862) 12(-3.675,2.862) 13(-3.675,-2.862) 24(3.675,-2.862)
  rect 0.4x1.585 smd: 2(2.925,2.862) 3(2.275,2.862) 4(1.625,2.862) 5(0.975,2.862) 6(0.325,2.862) 7(-0.325,2.862) 8(-0.975,2.862) 9(-1.625,2.862) 10(-2.275,2.862) 11(-2.925,2.862) 14(-2.925,-2.862) 15(-2.275,-2.862) 16(-1.625,-2.862) 17(-0.975,-2.862) 18(-0.325,-2.862) 19(0.325,-2.862) 20(0.975,-2.862) 21(1.625,-2.862) 22(2.275,-2.862) 23(2.925,-2.862)
FTP_65
  rect 0.45x0.55 smd: 1(-0.425,0) 2(0.425,0)
FTP_65#2
  rect 0.45x0.55 smd: 1(0.425,0) 2(-0.425,0)
FTP_67
  rect 0.72x0.8 smd: 1(-0.64,0) 2(0.64,0)
FTP_67#2
  rect 0.72x0.8 smd: 1(0.64,0) 2(-0.64,0)
FTP_69
  round 2.6 hole 1.3: 1(0,-7) 2(0,7)
FTP_71
  round 1.8 hole 1.1: 1(0,0)
FTP_73
  round 2 hole 1: 1(-6.25,0) 2(6.25,0)
FTP_75
  round 2.2 hole 1.1: 1(-11.25,0) 2(11.25,0)
FTP_77
  round 2 hole 1: 1(-7.5,0) 2(7.5,0)
FTP_79
  round 2 hole 1: 1(0,0) 2(10,0)
FTP_81
  rect 1.1x2 smd: A(-2.25,0) C(2.25,0)
FTP_83
  rect 0.95x0.8 smd: A(-1.225,0)
  rect 1.85x1.1 smd: C(0.775,0)
FTP_85
  rect 1.212x1.2 smd: A(-1.494,0) C(1.494,0)
FTP_92
  custom 1.075x1.075 hole 5x3.3: 1(-3.25,-8)
FTP_94
  round 2 hole 1: 1(-3.6,-4.3) 2(3.6,-4.3)
  round 1.8 hole 0.9: 3(2.575,2.7) 4(-2.575,2.7)
FTP_96
  round 3.2 hole 1.6: 1(-8.89,6.35) 2(-8.89,-6.35) 6(-3.81,6.35) 7(-3.81,-6.35)
  round 2.2 hole 1.1: 3(8.89,6.35) 4(8.89,0) 5(8.89,-6.35)
FTP_98
  round 2.4 hole 1.2: 1(0,0) 2(10,0)
FTP_100
  round 1.8 hole 0.9: 1(-10,3.75) 2(-10,-3.75)
  round 2.6 hole 1.3: 3(6.5,-3.75) 4(10,3.75)
FTP_102
  round 3.175 hole 1.8: D(5.45,0) G(10.9,0) S(0,0)
FTP_106
  rect 1.405x3.4 smd: 1(2.902,0) 2(-2.902,0)
FTP_108
  round 1.8 hole 0.9: 1(-2.5,0)
  round 2.2 hole 1.1: 2(2.5,0)
FTP_110
  round 3.3 hole 1.8: 1(-12,10) 2(-12,-10) 3(12,-10) 4(12,10)
FTP_112
  rect 0.825x1.795 smd: 1(-2.042,-2.558) 4(2.042,-2.558) 5(2.042,2.558) 8(-2.042,2.558)
  rect 0.55x1.795 smd: 2(-0.635,-2.558) 3(0.635,-2.558) 6(0.635,2.558) 7(-0.635,2.558)
FTP_116
  round 3.8 hole 2.8: 1(0,0)
FTP_118
  round 3 hole 1.5: 1(0,-11) 2(0,11)
FTP_120
  round 2.2 hole 1.1: 1(-3.75,1.3) 2(3.75,-1.3)
FTP_122
  rect 0.8x1.3 smd: 1(-1.27,-4.75) 2(0,-4.75) 3(1.27,-4.75) 4(1.27,4.75) 5(0,4.75) 6(-1.27,4.75)
FTP_124
  custom 1.2x1.2 hole 10.3x3.8: 1(10,-20) 2(-10,20)
FTP_126
  round 4 hole 2: 1(-20.25,7.5) 2(-20.25,-7.5)
  custom 0.6x0.6 hole 8.3x1.4: 3(17.5,-12.5) 4(17.5,-7.5) 5(17.5,7.5) 6(17.5,12.5)
FTP_128
  rect 0.6x1.46 smd: 1(-3.025,-2.925) 10(3.025,-2.925) 11(3.025,2.925) 20(-3.025,2.925)
  rect 0.4x1.46 smd: 2(-2.275,-2.925) 3(-1.625,-2.925) 4(-0.975,-2.925) 5(-0.325,-2.925) 6(0.325,-2.925) 7(0.975,-2.925) 8(1.625,-2.925) 9(2.275,-2.925) 12(2.275,2.925) 13(1.625,2.925) 14(0.975,2.925) 15(0.325,2.925) 16(-0.325,2.925) 17(-0.975,2.925) 18(-1.625,2.925) 19(-2.275,2.925)

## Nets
P12V: C92.2(TP-1) C93.2(TP-1) C100.2(TP-1) CN6.1 IC8.1 IC8.6 Q15.5 Q15.6 Q15.7 Q15.8 Q16.5 Q16.6 Q16.7 Q16.8 Q17.5 Q17.6 Q17.7 Q17.8 Q18.5 Q18.6 Q18.7 Q18.8 Q19.5 Q19.6 Q19.7 Q19.8 Q20.5 Q20.6 Q20.7 Q20.8 Q21.5 Q21.6 Q21.7 Q21.8 Q22.5 Q22.6 Q22.7 Q22.8 Q23.5 Q23.6 Q23.7 Q23.8 Q24.5 Q24.6 Q24.7 Q24.8
VCC3R3_1: C95.2(TP-1) C96.2(TP-1) C97.2(TP-1) C98.2(TP-1) IC21.5 IC22.5 IC23.5 IC24.5 R117.2(TP-1) R157.1(TP-1) R160.1(TP-1) R163.1(TP-1) R166.1(TP-1) R186.2(TP-1) R188.2(TP-1) R190.2(TP-1) R192.2(TP-1)
VCC12R0_1: C70.2(TP-1) D48.C IC2.1 IC2.8 IC20.1 R83.2(TP-1) R87.2(TP-1) R116.2(TP-1) R120.1(TP-1) R121.1(TP-1) R122.1(TP-1) R123.1(TP-1) R130.1(TP-1)
VCC12R0_2: R49.1(TP-1) R118.2(TP-1) R124.1(TP-1) R125.1(TP-1)
$BN000001: R90.2(TP-1) R227.1(TP-1)
$BN000002: R2.2(TP-1) R228.1(TP-1)
CONN002: C19.1(TP-1) D24.A IC4.11 Q3.S Q4.D R31.1(TP-1) T5.1 T6.1
CONN003: D18.C D19.A L3.2(TP-1) T5.2 T6.2
CONN004: C2.2(TP-1) C3.2(TP-1) C4.2(TP-1) C5.2(TP-1) C6.2(TP-1) C59.2(TP-1) C102.2(TP-1) CN8.1(TP-1) IC8.7 L5.2(TP-1) L6.2(TP-1) Q15.1 Q15.2 Q15.3 Q16.1 Q16.2 Q16.3 Q17.1 Q17.2 Q17.3 Q18.1 Q18.2 Q18.3 Q19.1 Q19.2 Q19.3 Q20.1 Q20.2 Q20.3 Q21.1 Q21.2 Q21.3 Q22.1 Q22.2 Q22.3 Q23.1 Q23.2 Q23.3 Q24.1 Q24.2 Q24.3 R75.2(TP-1) R77.1(TP-1) R78.1(TP-1) R106.1(TP-1) R107.2(TP-1) R128.2(TP-1) R129.1(TP-1) R199.2(TP-1) R200.2(TP-1) R201.2(TP-1) R202.2(TP-1) R203.2(TP-1) TP31.1 TP40.1
CS: D14.C R67.2(TP-1) R185.2(TP-1)
CSA: D13.C D33.C R7.2(TP-1) R87.1(TP-1) R170.1(TP-1) TP2.1
CSB: D12.C D31.C R8.2(TP-1) R83.1(TP-1) R169.1(TP-1) TP1.1
FG1: CN1.2
FG2: C79.1(TP-1)
FG3: C32.1(TP-1) C64.1(TP-1) C78.1(TP-1)
FG4: C31.1(TP-1) C63.1(TP-1)
FG5: C101.2(TP-1)
FG6: C93.1(TP-1) C94.2(TP-1) R205.1(TP-1) R206.1(TP-1)
FG7: R204.1(TP-1)
GDA: C81.2(TP-1) IC2.2 IC3.14 TP5.1
GDB: C80.2(TP-1) IC2.4 IC3.17 TP6.1
HS1_1: R224.2(TP-1)
HS1_2: R225.2(TP-1)
INPUT12V_1: CN2.1 R116.1(TP-1)
INPUT12V_2: CN4.1 R118.1(TP-1)
LGND: C2.1(TP-1) C3.1(TP-1) C4.1(TP-1) C5.1(TP-1) C6.1(TP-1) C23.1(TP-1) C24.1(TP-1) C25.1(TP-1) C26.1(TP-1) C27.1(TP-1) C51.1(TP-1) C60.1(TP-1) C61.1(TP-1) C88.1(TP-1) C89.1(TP-1) C90.1(TP-1) C91.1(TP-1) C92.1(TP-1) C94.1(TP-1) C99.1(TP-1) C100.1(TP-1) C102.1(TP-1) CN5.1 CN7.1 CN8.2(TP-1) CN10.2(TP-1) D26.A D27.A D28.A D29.A IC6.3 IC7.3 IC8.3 IC8.4 IC10.24 Q7.1 Q7.2 Q7.3 Q8.1 Q8.2 Q8.3 Q9.1 Q9.2 Q9.3 Q10.1 Q10.2 Q10.3 Q11.1 Q11.2 Q11.3 Q12.1 Q12.2 Q12.3 Q13.1 Q13.2 Q13.3 Q14.1 Q14.2 Q14.3 Q25.1 Q25.2 Q25.3 Q26.1 Q26.2 Q26.3 Q27.1 Q27.2 Q27.3 Q28.1 Q28.2 Q28.3 R9.1(TP-1) R19.1(TP-1) R21.1(TP-1) R22.1(TP-1) R25.1(TP-1) R43.1(TP-1) R45.1(TP-1) R48.1(TP-1) R50.1(TP-1) R51.1(TP-1) R52.1(TP-1) R53.1(TP-1) R54.1(TP-1) R55.1(TP-1) R56.1(TP-1) R61.1(TP-1) R64.1(TP-1) R66.1(TP-1) R70.1(TP-1) R76.1(TP-1) R105.1(TP-1) R180.1(TP-1) R181.1(TP-1) R182.1(TP-1) R184.1(TP-1) R185.1(TP-1) R194.2(TP-1) R195.2(TP-1) R196.2(TP-1) R197.2(TP-1) R199.1(TP-1) R200.1(TP-1) R201.1(TP-1) R202.1(TP-1) R203.1(TP-1) R204.2(TP-1) R205.2(TP-1) R206.2(TP-1) R208.1(TP-1) R209.1(TP-1) T4.3 TP41.1 TP42.1
OUTA1: IC21.4 R111.1(TP-1) R187.2(TP-1)
OUTA2: IC10.22 R149.2(TP-1)
OUTB1: IC22.4 R110.1(TP-1) R189.2(TP-1)
OUTB2: IC10.21 R150.2(TP-1)
OUTC1: IC23.4 R113.1(TP-1) R191.2(TP-1)
OUTC2: IC10.20 R151.2(TP-1)
OUTD1: IC24.4 R112.1(TP-1) R193.2(TP-1)
OUTD2: IC10.19 R152.2(TP-1)
OUTE: IC6.2 IC7.2 IC10.18 TP23.1 TP25.1
OUTF: IC6.4 IC7.4 IC10.17 TP24.1 TP26.1
PFC_OUT: C1.2(TP-1) C7.2(TP-1) D1.C D2.C D3.1 R92.2(TP-1) R178.2(TP-1) T4.2 TP44.1
PFC_VIN: D8.C D9.C R95.2(TP-1)
PN: C1.1(TP-1) C7.1(TP-1) C34.1(TP-1) C35.1(TP-1) C36.1(TP-1) C37.1(TP-1) C38.1(TP-1) C39.1(TP-1) C40.1(TP-1) C42.1(TP-1) C43.1(TP-1) C45.1(TP-1) C47.1(TP-1) C48.1(TP-1) C49.1(TP-1) C50.1(TP-1) C53.1(TP-1) C54.1(TP-1) C55.1(TP-1) C56.1(TP-1) C57.1(TP-1) C58.1(TP-1) C62.1(TP-1) C66.1(TP-1) C67.1(TP-1) C70.1(TP-1) C71.1(TP-1) C72.1(TP-1) C73.1(TP-1) C74.1(TP-1) C75.1(TP-1) C76.1(TP-1) C77.1(TP-1) C80.1(TP-1) C81.1(TP-1) C82.1(TP-1) C83.1(TP-1) C84.1(TP-1) C85.1(TP-1) C86.1(TP-1) C87.1(TP-1) C95.1(TP-1) C96.1(TP-1) C97.1(TP-1) C98.1(TP-1) C101.1(TP-1) CN3.1 D3.4 D18.A D22.A D25.A D49.A D50.C IC2.3 IC3.16 IC4.3 IC4.5 IC5.3 IC5.5 IC11.1 IC13.4 IC14.4 IC15.4 IC16.4 IC20.2 IC21.3 IC22.3 IC23.3 IC24.3 Q1.S Q2.S Q4.S Q6.S R2.1(TP-1) R7.1(TP-1) R8.1(TP-1) R29.1(TP-1) R33.1(TP-1) R71.1(TP-1) R73.1(TP-1) R90.1(TP-1) R93.1(TP-1) R96.1(TP-1) R98.1(TP-1) R99.1(TP-1) R100.1(TP-1) R101.1(TP-1) R102.1(TP-1) R103.1(TP-1) R104.1(TP-1) R174.1(TP-1) R175.1(TP-1) R176.1(TP-1) R179.1(TP-1) R187.1(TP-1) R189.1(TP-1) R191.1(TP-1) R193.1(TP-1) R198.1(TP-1) R220.1(TP-1) R221.1(TP-1) R222.1(TP-1) R223.1(TP-1) R224.1(TP-1) R225.1(TP-1) T2.2 T3.2 TP43.1 TP45.1
SIG1: C30.2(TP-1) C78.2(TP-1) F1.2(TP-1) L11.2 R79.2(TP-1) RV1.1(TP-1)
SIG2: C30.1(TP-1) C79.2(TP-1) CN1.3 L11.3 R80.1(TP-1) RV1.2(TP-1)
SIG6: C33.1(TP-1) C63.2(TP-1) C65.1(TP-1) D3.3 D9.A L2.1(TP-1) L12.4
SIG8: C33.2(TP-1) C65.2(TP-1) D3.2 D8.A IC20.3 L1.1(TP-1) R138.2(TP-1)
SIG9: IC1.2 IC1.3 R79.1(TP-1)
SIG10: IC1.6 IC1.7 R80.2(TP-1)
SIG11: D2.A L2.2(TP-1) T2.4
SIG12: D1.A L1.2(TP-1) T3.4
SIG15: D12.A R81.2(TP-1) T2.1
SIG16: C34.2(TP-1) R81.1(TP-1)
SIG18: Q2.D T2.3
SIG20: D13.A R85.2(TP-1) T3.1
SIG21: C36.2(TP-1) R85.1(TP-1)
SIG22: Q1.D T3.3
SIG23: FB1.1(TP-1) R71.2(TP-1) R72.2(TP-1) R108.2(TP-1)
SIG24: C35.2(TP-1) D31.A R82.2(TP-1) R172.2(TP-1)
SIG25: C37.2(TP-1) D33.A R86.2(TP-1) R173.2(TP-1)
SIG27: FB2.1(TP-1) R73.2(TP-1) R74.2(TP-1) R109.2(TP-1)
SIG30: D32.C D38.A D39.C IC2.7 R86.1(TP-1)
SIG39: R89.2(TP-1) R91.1(TP-1)
SIG40: R91.2(TP-1) R92.1(TP-1)
SIG43: C45.2(TP-1) C46.2(TP-1) IC3.11
SIG44: C46.1(TP-1) R99.2(TP-1)
SIG45: C43.2(TP-1) C44.2(TP-1) IC3.12
SIG46: C44.1(TP-1) R98.2(TP-1)
SIG47: C40.2(TP-1) C41.2(TP-1) IC3.3
SIG48: C41.1(TP-1) R93.2(TP-1)
SIG49: C39.2(TP-1) IC3.4 R89.1(TP-1) R227.2(TP-1) TP8.1
SIG50: C49.2(TP-1) IC3.18
SIG51: C50.2(TP-1) IC3.1 R171.1(TP-1)
SIG52: IC3.19 R100.2(TP-1) R198.2(TP-1)
SIG53: IC3.7 R101.2(TP-1) R176.2(TP-1)
SIG54: IC3.6 R102.2(TP-1) R175.2(TP-1)
SIG55: IC3.20 R103.2(TP-1) R174.2(TP-1)
SIG56: IC3.2 R104.2(TP-1)
SIG60: R94.2(TP-1) R95.1(TP-1)
SIG61: R1.2(TP-1) R94.1(TP-1)
SIG62: C38.2(TP-1) IC3.5 R1.1(TP-1) R228.2(TP-1) TP7.1
SIG65: C19.2(TP-1) D17.C IC4.13
SIG75: C18.2(TP-1) D16.C IC5.13
SIG82: Q6.G R29.2(TP-1) R136.2(TP-1) R137.2(TP-1) TP14.1
SIG86: C47.2(TP-1) C48.2(TP-1) D49.C IC3.15 R120.2(TP-1)
SIG89: C54.2(TP-1) IC5.1 R111.2(TP-1) TP38.1
SIG90: C53.2(TP-1) IC5.2 R110.2(TP-1) TP39.1
SIG91: C58.2(TP-1) C84.2(TP-1) C85.2(TP-1) IC4.7 R115.1(TP-1) R122.2(TP-1)
SIG92: D17.A R115.2(TP-1)
SIG93: C57.2(TP-1) IC4.1 R113.2(TP-1) TP9.1
SIG94: C56.2(TP-1) IC4.2 R112.2(TP-1) TP10.1
SIG95: D16.A R114.2(TP-1)
SIG100: D36.C R72.1(TP-1)
SIG101: D37.A R108.1(TP-1)
SIG102: D30.C D36.A D37.C IC2.5 R82.1(TP-1)
SIG104: C62.2(TP-1) C82.2(TP-1) C83.2(TP-1) IC2.6 R121.2(TP-1)
SIG105: D39.A R109.1(TP-1)
SIG106: D38.C R74.1(TP-1)
SIG115: D34.A Q9.5 Q9.6 Q9.7 Q9.8 Q10.5 Q10.6 Q10.7 Q10.8 Q27.5 Q27.6 Q27.7 Q27.8 T5.5
SIG116: D29.C D57.A D58.C IC7.7
SIG117: D28.C D55.A D56.C IC7.5
SIG118: Q9.4 Q27.4 R24.2(TP-1) R25.2(TP-1) R215.2(TP-1) R219.1(TP-1) TP20.1
SIG121: C60.2(TP-1) C90.2(TP-1) C91.2(TP-1) IC7.6 R124.2(TP-1)
SIG122: C59.1(TP-1) IC8.8
SIG124: C61.2(TP-1) C88.2(TP-1) C89.2(TP-1) IC6.6 R125.2(TP-1)
SIG126: D26.C D53.A D54.C IC6.7
SIG127: D27.C D51.A D52.C IC6.5
SIG128: Q13.4 Q26.4 R20.2(TP-1) R21.2(TP-1) R213.2(TP-1) R217.1(TP-1) TP19.1
SIG134: D20.A Q13.5 Q13.6 Q13.7 Q13.8 Q14.5 Q14.6 Q14.7 Q14.8 Q26.5 Q26.6 Q26.7 Q26.8 T6.5 TP29.1
SIG135: D21.A Q11.5 Q11.6 Q11.7 Q11.8 Q12.5 Q12.6 Q12.7 Q12.8 Q25.5 Q25.6 Q25.7 Q25.8 T6.6 TP30.1
SIG136: IC8.5 R6.1(TP-1)
SIG138: C27.2(TP-1) D20.C D21.C R76.2(TP-1) R77.2(TP-1) R78.2(TP-1) R128.1(TP-1) TP27.1
SIG141: Q15.4 Q16.4 Q17.4 Q18.4 Q19.4 Q20.4 Q21.4 Q22.4 Q23.4 Q24.4 R6.2(TP-1) TP28.1
SIG148: IC10.6 R51.2(TP-1) R180.2(TP-1)
SIG149: IC10.7 R52.2(TP-1) R181.2(TP-1)
SIG150: IC10.8 R53.2(TP-1) R182.2(TP-1)
SIG151: IC10.9 R54.2(TP-1)
SIG152: C25.2(TP-1) CN10.1(TP-1) IC10.5 R50.2(TP-1)
SIG154: IC10.2 R44.1(TP-1) R45.2(TP-1)
SIG156: C20.1(TP-1) C22.1(TP-1) IC10.3 R42.1(TP-1) R43.2(TP-1) R47.2(TP-1)
SIG157: R42.2(TP-1) R46.2(TP-1) R75.1(TP-1) TP33.1
SIG167: C21.1(TP-1) R47.1(TP-1)
SIG168: C21.2(TP-1) C22.2(TP-1) IC10.4 R48.2(TP-1) TP32.1
SIG170: C20.2(TP-1) R46.1(TP-1)
SIG171: IC10.14 R65.1(TP-1) R66.2(TP-1) R209.2(TP-1) R211.1(TP-1)
SIG172: IC10.13 R63.1(TP-1) R64.2(TP-1) R208.2(TP-1) R210.1(TP-1)
SIG173: C26.2(TP-1) IC10.15 R63.2(TP-1) R65.2(TP-1) R69.1(TP-1) R70.2(TP-1)
SIG174: R59.2(TP-1) R67.1(TP-1) R69.2(TP-1)
SIG175: R59.1(TP-1) R60.2(TP-1) R62.1(TP-1)
SIG177: IC10.12 R60.1(TP-1) R61.2(TP-1) R184.2(TP-1)
SIG179: IC10.10 R55.2(TP-1) R57.1(TP-1) R207.1(TP-1)
SIG181: IC10.11 R56.2(TP-1) R58.1(TP-1)
SIG183: C23.2(TP-1) C24.2(TP-1) IC10.23 R49.2(TP-1)
SIG185: C67.2(TP-1) IC11.3 R117.1(TP-1)
SIG193: CN1.1 F1.1(TP-1)
SIG199: C32.2(TP-1) C52.2(TP-1) L11.1 L12.2
SIG200: C31.2(TP-1) C52.1(TP-1) L11.4 L12.3
SIG205: Q4.G R33.2(TP-1) R134.2(TP-1) R135.2(TP-1) TP12.1
SIG206: Q3.G R31.2(TP-1) R126.2(TP-1) R127.2(TP-1) TP11.1
SIG223: C66.2(TP-1) IC11.2 R130.2(TP-1)
SIG228: IC13.5 R153.2(TP-1)
SIG229: C71.2(TP-1) IC13.6 R157.2(TP-1)
SIG230: IC13.1 R149.1(TP-1) TP34.1
SIG231: C72.2(TP-1) IC14.6 R160.2(TP-1)
SIG234: IC14.5 R154.2(TP-1)
SIG236: IC14.1 R150.1(TP-1) TP35.1
SIG237: C73.2(TP-1) IC15.6 R163.2(TP-1)
SIG242: IC15.5 R155.2(TP-1)
SIG243: IC16.1 R152.1(TP-1) TP37.1
SIG245: IC16.5 R156.2(TP-1)
SIG246: C74.2(TP-1) IC16.6 R166.2(TP-1)
SIG247: IC15.1 R151.1(TP-1) TP36.1
SIG249: C18.1(TP-1) D23.A IC5.11 L3.1(TP-1) Q5.S Q6.D R28.1(TP-1) TP15.1
SIGN254: D30.A R172.1(TP-1)
SIGN255: D32.A R173.1(TP-1)
SIGN256: C77.2(TP-1) IC3.10 R96.2(TP-1) R97.1(TP-1) R177.1(TP-1)
SIGN260: C76.2(TP-1) IC3.9 R170.2(TP-1)
SIGN262: C75.2(TP-1) IC3.8 R169.2(TP-1)
SIGN266: FB1.2(TP-1) Q2.G TP3.1
SIGN267: FB2.2(TP-1) Q1.G TP4.1
SIGN269: D23.C D42.A D43.C IC5.12
SIGN270: C55.2(TP-1) C86.2(TP-1) C87.2(TP-1) IC5.7 R114.1(TP-1) R123.2(TP-1)
SIGN271: R178.1(TP-1) R179.2(TP-1)
SIGN273: C51.2(TP-1) D34.C D35.C R105.2(TP-1) R106.2(TP-1) R107.1(TP-1) R129.2(TP-1)
SIGN275: D48.A D50.A
SIGN284: IC13.3 R194.1(TP-1)
SIGN287: IC14.3 R195.1(TP-1)
SIGN289: IC16.3 R197.1(TP-1)
SIGN291: IC15.3 R196.1(TP-1)
SIGN304: IC21.2 R153.1(TP-1) R186.1(TP-1)
SIGN305: IC22.2 R154.1(TP-1) R188.1(TP-1)
SIGN314: IC23.2 R155.1(TP-1) R190.1(TP-1)
SIGN315: IC24.2 R156.1(TP-1) R192.1(TP-1)
SIGN316: D40.C R126.1(TP-1)
SIGN317: D41.A R127.1(TP-1)
SIGN318: D24.C D40.A D41.C IC4.12
SIGN319: D42.C R132.1(TP-1)
SIGN320: D43.A R133.1(TP-1)
SIGN321: Q5.G R28.2(TP-1) R132.2(TP-1) R133.2(TP-1) TP13.1
SIGN322: D22.C D46.A D47.C IC5.6
SIGN323: D46.C R136.1(TP-1)
SIGN324: D47.A R137.1(TP-1)
SIGN325: D25.C D44.A D45.C IC4.6
SIGN326: D45.A R135.1(TP-1)
SIGN327: D44.C R134.1(TP-1)
SIGN336: D53.C R20.1(TP-1)
SIGN337: D54.A R213.1(TP-1)
SIGN338: D51.C R18.1(TP-1)
SIGN339: D52.A R212.1(TP-1)
SIGN340: Q11.4 Q12.4 R18.2(TP-1) R19.2(TP-1) R212.2(TP-1) R216.1(TP-1) TP21.1
SIGN341: D57.C R24.1(TP-1)
SIGN342: D58.A R215.1(TP-1)
SIGN343: Q7.4 Q8.4 R22.2(TP-1) R23.2(TP-1) R214.2(TP-1) R218.1(TP-1) TP22.1
SIGN344: D55.C R23.1(TP-1)
SIGN345: D56.A R214.1(TP-1)
SIGN351: Q25.4 R216.2(TP-1)
SIGN352: Q14.4 R217.2(TP-1)
SIGN353: Q28.4 R218.2(TP-1)
SIGN354: Q10.4 R219.2(TP-1)
SIGN355: D19.C Q3.D Q5.D T4.1
SIGN356: D14.A R9.2(TP-1) T4.5
SIGN360: L5.1(TP-1) T5.3 T5.4 TP18.1
SIGN361: D35.A Q7.5 Q7.6 Q7.7 Q7.8 Q8.5 Q8.6 Q8.7 Q8.8 Q28.5 Q28.6 Q28.7 Q28.8 T5.6
SIGN362: L6.1(TP-1) T6.3 T6.4 TP17.1
SIGN364: C64.2(TP-1) IC20.4 L12.1 R138.1(TP-1)
SIGN366: HS1.1 R220.2(TP-1)
SIGN369: HS2.1 R221.2(TP-1)
SIGN371: HS3.1 R222.2(TP-1)
SIGN373: HS4.1 R223.2(TP-1)
VREF: C99.2(TP-1) IC10.1 R44.2(TP-1) R57.2(TP-1) R58.2(TP-1) R62.2(TP-1) R207.2(TP-1) R210.2(TP-1) R211.2(TP-1)
VREF_PFC: C42.2(TP-1) IC3.13 R97.2(TP-1) R171.2(TP-1) R177.2(TP-1)

Pads without a net: D22 NC; D23 NC; D24 NC; D25 NC; D26 NC; D27 NC; D28 NC; D29 NC; IC1 1 4 5 8; IC4 4 8 9 10 14; IC5 4 8 9 10 14; IC6 1 8; IC7 1 8; IC8 2; IC10 16; IC11 4 5; IC13 2; IC14 2; IC15 2; IC16 2; IC21 1; IC22 1; IC23 1; IC24 1; T4 4 6 7

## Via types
v1: diameter 1.397, hole 0.8, TOP to BOTTOM, 226 vias
v2: diameter 0.55, hole 0.3, TOP to BOTTOM, 257 vias
v3: diameter 6, hole 3.3, TOP to BOTTOM, 6 vias
v4: diameter 7, hole 3.2, TOP to BOTTOM, 6 vias
v5: diameter 4.45, hole 2.225, TOP to BOTTOM, 22 vias
v6: diameter 10, hole 4.2, TOP to BOTTOM, 1 via

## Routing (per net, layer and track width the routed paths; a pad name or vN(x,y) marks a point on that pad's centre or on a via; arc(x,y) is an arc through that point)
P12V: length 27.6
  BOTTOM w0.45: 272.19,29.82 272.19,30.76 271.35,31.6 270.3,31.6 269.51,32.38 269.51,33.29 ; 276.85,42.85 276.55,42.85 273.2,39.5 273.2,27.2 272.9,26.9 272.32,26.9 C100.2 272.19,27.57 272.19,28.56
  BOTTOM w0.55: IC8.6 269.51,33.29
  BOTTOM w0.825: 272.19,28.56 IC8.1 272.19,29.82
  vias: v1(279.1,62.4) v1(279.1,59.4) v1(281.1,60.9) v1(281.1,57.9) v1(283.1,62.4) v1(283.1,59.4) v1(285.1,60.9) v1(285.1,57.9) v1(287.1,62.4) v1(287.1,59.4) v1(289.1,60.9) v1(289.1,57.9) v1(291.1,62.4) v1(291.1,59.4) v1(293.1,60.9) v1(293.1,57.9) v1(295.1,62.4) v1(295.1,59.4) v1(297.1,60.9) v1(297.1,57.9) v1(299.1,62.4) v1(299.1,59.4) v1(301.1,60.9) v1(301.1,57.9) v3(281.5,52.5) v3(281.5,46) v3(297.5,52.5) v5(271,67.05) v5(275,67.05) v5(277.5,67.05) v5(281.5,67.05) v5(284,67.05) v5(288,67.05) v5(290.5,67.05) v5(294.5,67.05) v5(297,67.05) v5(301,67.05)
VCC3R3_1: length 61.5
  TOP w0.3: 219.74,2.65 219.3,2.65 219.07,2.88 C98.2 ; 224.96,2.88 224.75,2.38 224.75,2.2 v2(224.5,1.95) 223.98,2.47 R192.2 ; R163.1 224.96,6.92 224.7,6.66 223.72,6.66 ; 219.87,6.85 219.09,6.85 218.78,6.97 ; v2(223.7,5.2) 223.5,5.4 223.5,6.44 ; v2(217.7,3.25) 218.07,2.88 218.43,2.88 ; 218.43,6.97 218.03,6.97 v2(217.7,7.3)
  TOP w0.45: 218.78,6.97 C97.2 218.43,6.97 ; 218.43,2.88 C98.2
  TOP w0.6: 219.74,2.65 IC24.5 ; IC23.5 219.87,6.85
  TOP w0.72: 223.72,6.66 R190.2 223.5,6.44 ; 224.96,2.88 R166.1
  CONDUCTIVE4 w0.5: 220.85,4.35 219.75,3.25 v2(217.7,3.25) ; v2(224.5,1.95) 224.5,4.4 v2(223.7,5.2) 223.7,6.35 222.75,7.3 223.7,8.25 v2(223.7,10)
  CONDUCTIVE4 w1: 220.85,4.35 220.85,6.5 ; 220.85,6.5 220.05,7.3 ; 220.85,6.5 220.85,7.3 ; 220.85,6.5 221.65,7.3 ; 220.05,7.3 v2(217.7,7.3) 215.3,9.7 210.9,9.7 206.15,14.45 v2(206.15,15) v2(206.15,16.25) ; 220.05,7.3 220.85,7.3 ; 220.85,7.3 221.65,7.3 ; 221.65,7.3 222.75,7.3
  BOTTOM w0.3: 218.88,3.73 219.25,3.73 219.59,4.07 220,4.25 ; 223.6,4.36 223.6,4.9 v2(223.7,5.2) ; v2(217.7,3.25) 218.18,3.73 218.53,3.73 ; 223.6,9.16 223.6,9.7 v2(223.7,10) ; 218.86,8.03 219.12,8.03 219.5,8.4 219.93,8.55 ; 224.89,8.8 224.34,8.8 223.82,8.94 ; 224.9,4.3 224.34,4.3 223.82,4.14 ; 218.64,8.03 217.88,8.03 217.7,7.85 v2(217.7,7.3)
  BOTTOM w0.45: 218.64,8.03 C95.2 218.86,8.03 ; 218.53,3.73 C96.2 218.88,3.73
  BOTTOM w0.6: IC22.5 220,4.25 ; IC21.5 219.93,8.55
  BOTTOM w0.72: 223.82,8.94 R186.2 223.6,9.16 ; R157.1 224.89,8.8 ; 223.82,4.14 R188.2 223.6,4.36 ; R160.1 224.9,4.3
VCC12R0_1: length 376.8
  TOP w0.3: IC20.1 91.95,69.8 90.35,71.4 90.35,73.45 89.38,74.42 88.84,74.42 ; 134.34,1.7 133.8,1.7 v2(133.5,2) ; v2(144.7,48.9) 140.96,48.9 140.66,48.6 140.66,47.98 ; 88.62,74.42 88.3,74.35 87.47,74.35 ; v2(88.8,75.2) 88.8,74.45
  TOP w0.4: D48.C 87.47,74.35
  TOP w0.45: R121.1 147.84,39.11 v2(147.9,38.7) ; 146.33,92.86 144.26,92.86 v2(141.45,90.05) v2(141.45,88.8) ; 88.8,74.45 C70.2 ; C70.2 88.84,74.42 ; C70.2 88.62,74.42 ; R122.1 173.1,60.46 v2(173.1,41.8) v2(173.1,40.55) ; 148.1,39.7 149.44,39.7 R83.2
  TOP w0.5: v2(144.7,36.9) 144.7,37.6 143.7,38.6 142,38.6 140.66,39.94 ; 138.94,41.31 138.94,40.6 139.6,39.94 140.66,39.94 ; 208.7,7.73 208.7,11.1 206.2,13.6 205.46,13.6 ; 140.66,39.94 140.66,41.35
  TOP w0.72: 138.94,41.31 R87.2 ; 205.46,13.6 R130.1 ; 134.34,1.7 R120.1 ; 208.7,7.44 208.7,7.73 ; 146.33,92.86 R123.1 ; R121.1 148.1,39.7
  TOP w0.825: 140.66,47.98 IC2.8 ; 140.66,41.35 IC2.1
  CONDUCTIVE4 w1: 126.4,43.55 126.4,47 ; 126.4,43.55 v2(126.4,42.3) v2(125.15,42.3) 126.4,43.55 ; 126.4,47 127.1,47.7 ; 126.4,47 126.4,47.7 ; 186.5,14.65 186.5,30.9 178.4,39 173.8,39 ; 186.5,14.65 187.3,13.85 ; 186.5,14.65 185.7,13.85 ; 186.5,14.65 186.5,13.85 ; 187.3,13.85 186.5,13.85 ; 187.3,13.85 200.45,13.85 207.1,7.2 v2(209.6,7.2) ; 186.5,13.85 185.7,13.85 ; v2(147.9,38.7) 146.4,40.2 146.4,47.2 v2(144.7,48.9) 143,48.9 141.8,47.7 127.1,47.7 ; v2(147.9,38.7) 146.1,36.9 v2(144.7,36.9) ; v2(147.9,38.7) 160.2,38.7 161.2,37.7 168.3,37.7 169.6,39 172.4,39 ; 127.1,47.7 126.4,47.7 ; 127.1,47.7 126.4,48.4 ; 173.1,39 172.4,39 ; 173.1,39 173.8,39 ; 173.1,39 173.1,39.7 ; 172.4,39 173.1,39.7 ; 126.4,47.7 126.4,48.4 ; 173.8,39 173.1,39.7 ; v2(141.45,90.05) v2(141.45,88.8) 141.45,87.75 126.4,72.7 126.4,48.4 ; 173.1,39.7 v2(173.1,40.55) v2(173.1,41.8) ; v2(133.5,2) 149.85,18.35 157.6,18.35 162.1,13.85 185.7,13.85
  BOTTOM w1: v2(88.8,75.2) 98.35,75.2 106,67.55 106,51.25 114.95,42.3 v2(125.15,42.3) v2(126.4,42.3)
  vias: v2(209.6,8.45) v2(210.85,8.45) v2(210.85,7.2)
VCC12R0_2: length 160.7
  TOP w0.5: v2(221.85,59.2) v2(223.1,59.2) 225.5,59.2 226.6,58.1 226.6,53.15 228,51.75 228,50.63
  TOP w0.72: R124.1 228,50.63
  CONDUCTIVE3 w1: v2(223.1,59.2) v2(221.85,59.2) 221.85,60.45 ; v2(223.1,59.2) 225.5,59.2 228.3,56.4 228.3,38.85 224.1,34.65 224.1,26.8 235.1,15.8 v2(243.2,15.8) 247.95,20.55 259.85,20.55 274.65,5.75 v2(279.5,5.75) 280.5,5.75 ; v2(223.1,59.2) 221.85,60.45 ; 221.85,60.45 221.85,62.65 226.15,66.95 226.15,77.1 224.85,78.4 224.85,82.45 230.8,88.4 v2(230.8,89.55) v2(232.05,89.55)
  BOTTOM w0.3: v2(243.2,15.8) 244.15,15.8
  BOTTOM w0.72: 244.15,15.8 R49.1
  vias: v2(279.5,4.47) v2(280.75,5.75) v2(280.75,4.47)
$BN000001: length 1.2
  BOTTOM w0.3: 161.6,13.53 161.6,12.37
  BOTTOM w0.72: 161.6,12.37 R227.1 ; R90.2 161.6,13.53
$BN000002: length 1.5
  BOTTOM w0.3: R2.2 162.7,7.36 R228.1
CONN002: length 55.2
  TOP w0.3: 160.1,67.46 160.1,67.05 159.68,66.62 v2(159.32,66.62) ; v2(149.5,69.85) 149.5,70.45 149.1,70.85 D24.A ; Q3.S 142.5,76.25 146.19,72.56 148.38,72.56 ; 148.6,72.34 148.6,71.98 148.55,71.57
  TOP w0.55: 148.55,71.57 D24.A ; 160.1,67.46 IC4.11
  TOP w0.72: 148.38,72.56 R31.1 148.6,72.34
  CONDUCTIVE4 w0.2: v2(159.32,66.62) 159.32,67.03 155.28,71.08 150.72,71.08 v2(149.5,69.85)
  CONDUCTIVE4 w7: 172.6,106.55 170.32,106.55 164.5,100.27 164.5,86
  BOTTOM w0.3: v2(159.32,66.62) 159.32,66.15 158.82,65.65
CONN003: length 72.6
  TOP w3: T6.2 179.6,94 176.4,97.2 L3.2
  BOTTOM w1: D19.A 167.6,93 L3.2 167.5,101.5 D18.C
  BOTTOM w3: T6.2 184.5,92.25 184.5,82.09 176.65,74.24 176.65,60.65 181.2,56.1 T5.2
CONN004: length 119.1
  TOP w1: C2.2 281,115 ; C2.2 279.5,113.5 ; C2.2 278,115 ; C4.2 295,103.5 ; C4.2 296.5,102 ; C4.2 296.5,105 ; C5.2 296.5,88.5 ; C5.2 296.5,91.5 ; C5.2 295,90 ; C6.2 266.5,113.5 ; C6.2 268,115 ; C6.2 265,115 ; C3.2 294,115 ; C3.2 292.5,113.5 ; C3.2 291,115
  CONDUCTIVE4 w1: 270.15,36.7 v2(271.05,36.7) 271.05,35.8 ; 270.15,36.7 267.85,36.7 265.6,38.95 265.6,57.85 269.65,61.9 269.65,72.38 272.77,75.5 v1(274,75.5) ; 270.15,36.7 271.05,35.8 ; 271.05,35.8 271.05,22.8 v2(265.2,16.95)
  BOTTOM w0.3: 270.79,34.97 270.79,35.61 C59.2 ; R75.2 v2(265.2,16.95) ; 271.07,35.95 271.05,36.29 v2(271.05,36.7)
  BOTTOM w0.45: 271.07,35.95 C59.2
  BOTTOM w0.55: 270.79,34.97 IC8.7
  BOTTOM w1: C4.2 296.5,102 ; C4.2 295,103.5 ; C4.2 296.5,105 ; C5.2 296.5,88.5 ; C5.2 295,90 ; C5.2 296.5,91.5 ; C3.2 294,115 ; C3.2 291,115 ; C3.2 292.5,113.5 ; C6.2 268,115 ; C6.2 265,115 ; C6.2 266.5,113.5 ; C2.2 281,115 ; C2.2 279.5,113.5 ; C2.2 278,115
  vias: v1(271.3,108.55) v1(273.05,110.4) v1(274,81.5) v1(274,78.5) v1(276,80) v1(276,77) v1(276,74) v1(276.5,110.5) v1(278,108.5) v1(278,81.5) v1(278,78.5) v1(278,75.5) v1(279.5,110.5) v1(280,80) v1(280,77) v1(280,74) v1(281,108.5) v1(282,81.5) v1(282,78.5) v1(282,75.5) v1(282.5,110.5) v1(284,80) v1(284,77) v1(284,74) v1(286,81.5) v1(286,78.5) v1(286,75.5) v1(288,108.5) v1(288,80) v1(288,77) v1(288,74) v1(289.5,110.5) v1(290,103.5) v1(290,100.5) v1(290,97.5) v1(290,93) v1(290,90) v1(290,87) v1(290,81.5) v1(290,78.5) v1(290,75.5) v1(291,108.5) v1(292,102) v1(292,99) v1(292,96) v1(292,91.5) v1(292,88.5) v1(292.5,110.5) v1(294,108.5) v1(295.5,110.5) v1(296,80)
CS: length 26
  CONDUCTIVE4 w0.2: v2(238.75,14.1) 238.75,12.95 241,10.7 v2(242.8,10.7)
  BOTTOM w0.3: 227.04,22.05 227.85,22.05 228.9,21 232.2,21 238.4,14.8 238.4,14.45 v2(238.75,14.1) ; 224.08,21.3 224.75,21.3 225.5,22.05 226.01,22.05 ; v2(242.8,10.7) 243.75,10.7
  BOTTOM w0.55: D14.C 224.08,21.3
  BOTTOM w0.72: 243.75,10.7 R67.2
  BOTTOM w0.92: 227.04,22.05 R185.2 226.01,22.05
CSA: length 138.1
  TOP w0.3: 135.62,41.71 135.62,41.3 134.82,40.5 v2(130.4,40.5) ; 136.22,41.9 137.18,41.9 137.63,41.6 ; 108.4,75.5 107.23,76.52 v2(106.85,76.9)
  TOP w0.55: 136.22,41.9 D33.C 135.62,41.71
  TOP w0.72: R87.1 137.63,41.6
  TOP w2.1: 108.4,75.5 TP2.1
  CONDUCTIVE3 w0.2: v2(165.1,3.25) 159.85,3.25 159.3,3.8 159.3,14.5 153,20.8 153,34.25 149.22,38.02 132.88,38.02 v2(130.4,40.5) 125,45.9 125,56.85 123.15,58.7 123.15,74.65 121.6,76.2 107.55,76.2 v2(106.85,76.9)
  BOTTOM w0.3: v2(106.85,76.9) 106.26,77.49 106.26,78.16 ; 163.76,1.7 164.7,1.7 165.1,2.1 v2(165.1,3.25) ; 107.81,80.42 106.92,80.42 106.26,80.3
  BOTTOM w0.55: 108,80.42 107.81,80.42
  BOTTOM w0.72: 163.76,1.7 R170.1
  BOTTOM w0.895: 106.26,80.3 R7.2 106.26,78.16
CSB: length 106.5
  TOP w0.3: 151.28,38 150.87,37.96 150.12,37.96 ; D31.C 151.88,37.23 152.1,37 v2(152.6,37) ; 125.03,75.5 126.6,75.65 v2(126.6,75.65)
  TOP w0.55: 151.28,38 D31.C
  TOP w0.72: R83.1 150.12,37.96
  TOP w2.1: 125.03,75.5 TP1.1
  CONDUCTIVE3 w0.2: v2(126.6,75.65) 127.3,74.95 127.3,73.2 126.85,72.75 126.85,52.35 129,50.2 132.1,50.2 142.5,39.8 149.8,39.8 v2(152.6,37) 156.6,33 156.6,22.29 163.1,15.79 163.1,5.1 v2(163.57,4.62)
  BOTTOM w0.3: v2(163.57,4.62) 163.57,3.86 163.54,3.32 ; 128.81,78.92 127.92,78.92 127.26,78.8 ; R8.2 126.6,77.7 126.2,77.3 126.2,76.05 v2(126.6,75.65)
  BOTTOM w0.55: 129,78.92 128.81,78.92
  BOTTOM w0.72: 163.54,3.32 R169.1
  BOTTOM w0.895: 127.26,78.8 R8.2
FG1:
  vias: v6(37.5,45.5)
FG2: length 20.5
  TOP w0: v4(8,4) 8,4.04 11.5,4.04 11.5,3.95
  TOP w2: C79.1 23.4,3.95 8.05,3.95 v4(8,4)
FG3: length 56.6
  BOTTOM w0.15: 61.25,48.5 63,46.75 v4(63,45.5) 65.53,42.97 76.12,42.97 C32.1
  BOTTOM w1.5: 65.5,43.25 C32.1 78.05,41.6 C64.1 ; C78.1 61.25,48.5
FG4: length 42.3
  BOTTOM w0.15: 81.5,1.25 79.3,3.45 v4(79.3,4) 79.3,7.5
  BOTTOM w1.5: C63.1 112.5,1.25 81.5,1.25
  BOTTOM w2: 79.3,7.5 C31.1
FG5: length 4.6
  BOTTOM w1.5: C101.2 197.5,2.15
FG7:
  vias: v4(302.5,121)
GDA: length 49.5
  TOP w0.3: 141.78,40.23 141.78,39.83 142.1,39.5 144.1,39.5 148.7,34.9 v2(148.7,34.2) ; 142.06,41.52 142,41.13 142,41.12 141.78,40.9 141.78,40.56 ; v2(151.8,6.5) 152.55,5.75 152.55,3.12 152.15,1.6
  TOP w0.45: 141.78,40.56 141.78,40.23
  TOP w0.55: IC2.2 142.06,41.52
  TOP w2.1: 152.15,1.6 TP5.1
  CONDUCTIVE3 w0.2: v2(151.8,6.5) 148,10.3 148,32.9 148.7,33.6 v2(148.7,34.2)
  BOTTOM w0.3: v2(151.8,6.5) 151.4,6.53 151.1,6.53
  BOTTOM w0.4: IC3.14 151.1,6.53
GDB: length 50.5
  TOP w0.3: 144.74,41.53 144.82,40.91 144.82,40.58 ; v2(149.85,33.4) 149.85,34.65 144.82,39.67 144.82,40.23 ; 145.05,1.6 146.95,1.6 148.2,2.85 148.2,5.2 151.5,8.5 v2(151.8,8.5)
  TOP w0.45: 144.82,40.58 144.82,40.23
  TOP w0.825: 144.74,41.53 IC2.4
  TOP w2.1: 145.05,1.6 TP6.1
  CONDUCTIVE3 w0.2: v2(149.85,33.4) 149.4,32.95 149.4,10.9 v2(151.8,8.5)
  BOTTOM w0.3: 151.09,8.47 151.39,8.47 v2(151.8,8.5)
  BOTTOM w0.4: IC3.17 151.09,8.47
